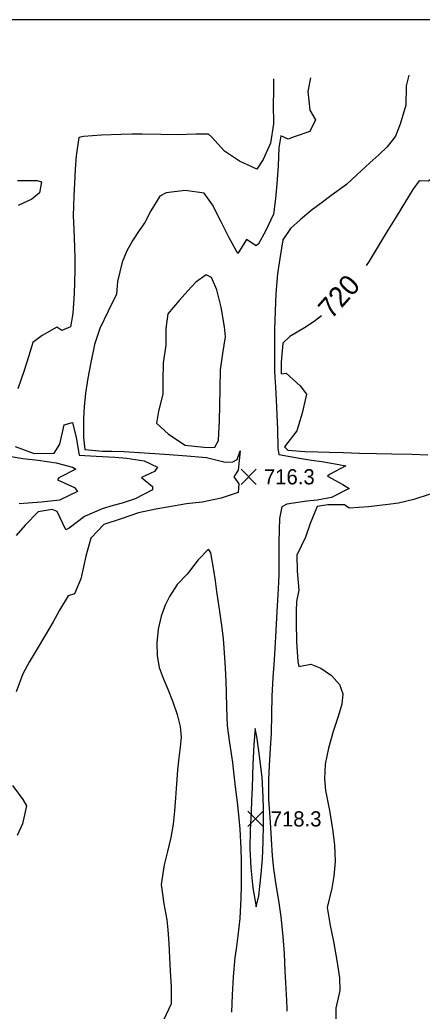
# Model space of a CAD drawing. Extents: x 2566079 to 2571326, y 424054 to 426896.
# Drawn here: x 2569092 to 2569490, y 425896 to 426874 of the extents above; entities that cross this region are included whole.
import ezdxf

# ---------------------------------------------------------------- set-up
doc = ezdxf.new("R2010")
doc.units = 0
for name, color, linetype in [('Contour_ADS_Label_Major', 7, 'Continuous'), ('Contour_ADS_Major', 7, 'Continuous'), ('Contour_ADS_Minor', 7, 'Continuous'), ('Contour_ADS_Spot_Elevation', 7, 'Continuous'), ('Contour_ADS_State_Plane_Border', 7, 'Continuous')]:
    doc.layers.add(name, color=color, linetype=linetype)

# ---------------------------------------------------------------- blocks, each defined once
blk = doc.blocks.new('S750')
at = {"layer": 'Contour_ADS_Spot_Elevation'}
for p, q in [((-0.5, 0.498), (0.5, -0.498)), ((-0.498, -0.5), (0.498, 0.5))]:
    blk.add_line(p, q, dxfattribs=at)

msp = doc.modelspace()

# ---------------------------------------------------------------- linework, layer by layer
at = {"layer": 'Contour_ADS_Major'}
for points in [[(2569582.66, 426821.92), (2569572.1, 426809.88), (2569562, 426794.76), (2569552.24, 426781.55), (2569544.76, 426771.47), (2569537.76, 426762.19), (2569528.08, 426749.94), (2569516.18, 426734.74), (2569508.52, 426725.45), (2569501.28, 426718.14), (2569495.52, 426714.64), (2569486.72, 426714.73), (2569480.41, 426706.26), (2569473.21, 426694.62), (2569463.96, 426679.49), (2569454.21, 426663.45), (2569445.24, 426648.69), (2569437.29, 426635.75), (2569434.53, 426631.41)], [(2569390.27, 426581.56), (2569383.06, 426576.26), (2569373.52, 426569.8), (2569359.02, 426561.22), (2569352.01, 426554.71), (2569350.53, 426536.08), (2569350.39, 426524.49), (2569355.37, 426525.28), (2569369.13, 426512.53), (2569375.37, 426504.58), (2569371.08, 426485.69), (2569366.03, 426468.09), (2569353.78, 426452.3), (2569356.92, 426449.22), (2569373.93, 426448.01), (2569386.62, 426447.52), (2569397.79, 426447.14), (2569411.88, 426446.71), (2569427.83, 426446.27), (2569444.45, 426445.88), (2569459.87, 426445.57), (2569479.69, 426445.26), (2569495.15, 426444.69)], [(2569497.72, 426405.76), (2569481.61, 426400.43), (2569466.45, 426397.04), (2569456.08, 426395.59), (2569436.75, 426393.31), (2569417.6, 426391.93), (2569413.11, 426395.14), (2569396.42, 426395.1), (2569386.08, 426393.6), (2569379.08, 426376.92), (2569374.35, 426363.4), (2569365.75, 426345.5), (2569366.36, 426329.89), (2569368, 426311.08), (2569365.66, 426299.97), (2569365.24, 426290.36), (2569365.2, 426279.42), (2569365.43, 426259.96), (2569366.84, 426240.54), (2569368.02, 426235.84), (2569379.87, 426238.16), (2569389.58, 426234.23), (2569400.09, 426226.88), (2569408.14, 426217.91), (2569411.29, 426208.66), (2569410.27, 426198.49), (2569406.59, 426186.31), (2569401.75, 426171.46), (2569397.11, 426155.19), (2569393.97, 426139.22), (2569393.25, 426125.07), (2569394.21, 426113.52), (2569397.89, 426095.25), (2569399.27, 426087.82), (2569401.23, 426075.39), (2569403.04, 426059.69), (2569403.71, 426043.42), (2569402.58, 426028.95), (2569400.39, 426017.14), (2569395.89, 425997.94), (2569398.72, 425980.35), (2569401.99, 425964.48), (2569405.53, 425945.76), (2569407.94, 425928.51), (2569408.22, 425916.08), (2569404.37, 425898.64), (2569404.52, 425886.62)]]:
    msp.add_lwpolyline(points, dxfattribs=at)
at = {"layer": 'Contour_ADS_Minor'}
for points in [[(2569379.34, 426816.45), (2569376.84, 426803.13), (2569378.88, 426784.63), (2569384.21, 426775.14), (2569378.86, 426763.58), (2569363.21, 426758.17), (2569357.32, 426756.1), (2569350.16, 426759.27), (2569348.16, 426747.33), (2569347.54, 426729.76), (2569346.15, 426712.08), (2569344.78, 426697.61), (2569343, 426681.99), (2569335.01, 426665.34), (2569327.94, 426652.85), (2569325.81, 426650.78), (2569316.12, 426657.05), (2569307.8, 426643.1), (2569299.2, 426658.71), (2569290.97, 426674.99), (2569282.58, 426691.15), (2569274.43, 426702.58), (2569255.56, 426705.27), (2569236.78, 426703.14), (2569230.49, 426699.62), (2569221.72, 426685.18), (2569215.62, 426673.92), (2569210.24, 426665.97), (2569203.99, 426656.47), (2569198.1, 426645.84), (2569193.56, 426634.67), (2569188.9, 426615.74), (2569187.78, 426603.02), (2569179.64, 426586.2), (2569171.32, 426569.24), (2569166.17, 426553.32), (2569161.97, 426534.05), (2569159.4, 426520.06), (2569157.2, 426505.5), (2569155.82, 426492.06), (2569155.15, 426480.54), (2569155.24, 426461.77), (2569156.68, 426449.77), (2569173.97, 426448.15), (2569183.09, 426448.17), (2569195.15, 426447.85), (2569210.07, 426446.99), (2569225.81, 426445.86), (2569239.86, 426444.8), (2569257.34, 426443.71), (2569276.84, 426442.08), (2569295.26, 426437.27), (2569302.84, 426437.73), (2569306.89, 426439.93), (2569309.98, 426448.64), (2569308.09, 426429.57), (2569303.64, 426422.83), (2569308.59, 426416.09), (2569307.87, 426407.46), (2569291.06, 426401.97), (2569272.57, 426397.9), (2569256.99, 426396.07), (2569238.07, 426393.1), (2569226.54, 426390.99), (2569209.56, 426387.48), (2569192.28, 426381.56), (2569175.31, 426375.87), (2569162.52, 426362.38), (2569157.46, 426344.68), (2569155.28, 426334.09), (2569152.42, 426322.29), (2569146.16, 426307.39), (2569140.03, 426305.58), (2569131.47, 426291.17), (2569125.21, 426279.96), (2569117.67, 426266.94), (2569109.44, 426253.28), (2569101.6, 426240.1), (2569095.34, 426228.48), (2569088.8, 426210.91)], [(2569342.98, 426815.47), (2569342.95, 426814.32), (2569342.75, 426802.86), (2569342.59, 426790.61), (2569342.89, 426771.28), (2569340.01, 426752.15), (2569332.75, 426735.88), (2569326.41, 426726.35), (2569309.39, 426734.31), (2569294.46, 426744.03), (2569281.97, 426757.86), (2569278.8, 426761.01), (2569266.17, 426760.86), (2569248.33, 426760.28), (2569231.43, 426760.76), (2569213.07, 426761.04), (2569202.82, 426760.85), (2569192.42, 426760.54), (2569173.14, 426759.83), (2569155.28, 426758.6), (2569150.74, 426757.59), (2569147.95, 426739.46), (2569147.02, 426726.42), (2569146.19, 426712.7), (2569145.57, 426700.19), (2569145.1, 426680.5), (2569145.6, 426666.83), (2569146.35, 426649.52), (2569146.56, 426638.23), (2569146.57, 426626.35), (2569146.33, 426614.75), (2569145.89, 426603.7), (2569144.68, 426583.99), (2569142.5, 426571), (2569133.87, 426567.35), (2569128.72, 426570.58), (2569114.47, 426562.42), (2569105.09, 426555.36), (2569100.86, 426541.17), (2569096.57, 426527.86), (2569090.36, 426509.57)], [(2569476.47, 426819.06), (2569473.79, 426808.46), (2569473.44, 426789.51), (2569467.96, 426770.96), (2569463.49, 426759.05), (2569455.07, 426748.28), (2569447.05, 426740.64), (2569438.04, 426732.6), (2569425.32, 426720.96), (2569414.91, 426711.42), (2569399.53, 426700.02), (2569389.82, 426692.85), (2569380.2, 426685.47), (2569369.07, 426676.51), (2569359.6, 426668.01), (2569351.92, 426656.7), (2569349.04, 426638.33), (2569346.92, 426623.02), (2569345.24, 426603.68), (2569344.35, 426586.26), (2569343.72, 426568.63), (2569343.73, 426558), (2569343.81, 426546.07), (2569343.99, 426526.37), (2569345, 426511.48), (2569345.59, 426498.75), (2569346.23, 426483.68), (2569346.75, 426469.99), (2569347.18, 426451.15), (2569348.14, 426445.01), (2569366.57, 426441.53), (2569380.36, 426439.45), (2569390.58, 426437.83), (2569407.32, 426435.1), (2569414.2, 426433.59), (2569398.32, 426425.24), (2569396.07, 426423.6), (2569411.49, 426415.32), (2569417.68, 426411.4), (2569400.15, 426402.51), (2569386.08, 426399.94), (2569375.7, 426398.8), (2569355.98, 426395.79), (2569351.06, 426393.32), (2569348.74, 426381.6), (2569348.51, 426370.6), (2569348.26, 426358.46), (2569348.29, 426338.81), (2569348.15, 426326.68), (2569347.79, 426318.68), (2569347.18, 426306.64), (2569346.26, 426290.12), (2569345.17, 426271.32), (2569344.07, 426253.03), (2569343.1, 426237.55), (2569342.3, 426224.95), (2569341.24, 426206.54), (2569340.96, 426188.22), (2569340.56, 426170.13), (2569339.72, 426154.75), (2569338.68, 426137.94), (2569337.81, 426123.86), (2569338.06, 426104.39), (2569338.59, 426096.02), (2569339.41, 426082.16), (2569340.46, 426065.36), (2569341.65, 426049.08), (2569342.9, 426036.08), (2569345.39, 426018.23), (2569347.77, 426004.82), (2569350.1, 425988.61), (2569352.12, 425969.24), (2569353.29, 425952.59), (2569353.99, 425935.04), (2569354.55, 425923.97), (2569355.57, 425906.24)], [(2569089.89, 426715.21), (2569109.47, 426715.37), (2569113.75, 426714.04), (2569111.8, 426702.91), (2569104.19, 426696.93), (2569090.75, 426690.64)], [(2569087.81, 426452.75), (2569106.55, 426445.98), (2569126.37, 426446.09), (2569131.85, 426454.96), (2569135.99, 426474.28), (2569144.33, 426476.31), (2569147.9, 426461.62), (2569151.01, 426444.34), (2569167.83, 426443.37), (2569186.26, 426442.29), (2569198.04, 426441.21), (2569215.08, 426438.5), (2569228.14, 426432.32), (2569225.43, 426428.17), (2569212.43, 426422.19), (2569223.29, 426413.18), (2569223.32, 426410.01), (2569206.33, 426401.04), (2569193.28, 426396.94), (2569184.37, 426394.59), (2569173.67, 426391.42), (2569156.36, 426383.7), (2569140.91, 426372.13), (2569137.6, 426370.67), (2569129.16, 426388.6), (2569124.32, 426390.54), (2569110.53, 426388.21), (2569097.47, 426375.07), (2569088.74, 426364.89)], [(2569078.09, 426443.98), (2569095.39, 426440.8), (2569110.57, 426439.22), (2569128.2, 426436.66), (2569144.5, 426432.28), (2569147.56, 426430.31), (2569130.76, 426421.81), (2569129.68, 426419.94), (2569146.39, 426412.45), (2569149.21, 426408.26), (2569131.59, 426399.7), (2569113.57, 426397.87), (2569100.47, 426396.95), (2569091.64, 426396.19)], [(2569301.66, 425894.59), (2569302.36, 425911.72), (2569303.24, 425929.42), (2569305.08, 425948.73), (2569306.52, 425959.34), (2569308.04, 425969.87), (2569310.06, 425987.22), (2569311.01, 426007.12), (2569311.3, 426020.13), (2569311.35, 426031.32), (2569311.29, 426044.05), (2569311.09, 426056.11), (2569310.05, 426075.18), (2569309.01, 426085.79), (2569307.53, 426099.27), (2569305.81, 426114.27), (2569304.09, 426128.67), (2569302.57, 426140.89), (2569299.86, 426160.52), (2569297.35, 426177.13), (2569296.64, 426195.26), (2569296.47, 426210.02), (2569296.07, 426221.08), (2569295.45, 426234.5), (2569294.57, 426249.08), (2569293.39, 426263.34), (2569291.9, 426276.17), (2569290.24, 426287.79), (2569288.54, 426298.8), (2569286.94, 426309.67), (2569285.44, 426320.35), (2569284, 426330.71), (2569280.85, 426347.88), (2569278.55, 426351.66), (2569268.49, 426341.01), (2569257.6, 426326.92), (2569247.86, 426316.73), (2569240.31, 426304.87), (2569235.87, 426296.14), (2569231.89, 426285.37), (2569229.02, 426272.67), (2569227.61, 426259.18), (2569227.93, 426246.28), (2569230.1, 426234.91), (2569233.75, 426224.31), (2569238.38, 426213.28), (2569243.39, 426201.02), (2569247.88, 426188.34), (2569250.81, 426176.42), (2569251.51, 426166.03), (2569250.65, 426156.25), (2569249.22, 426145.69), (2569248.03, 426133.39), (2569247.09, 426119.94), (2569246.22, 426106.29), (2569245.23, 426093.18), (2569243.77, 426080.29), (2569241.48, 426067.06), (2569238.26, 426053.25), (2569234.92, 426040), (2569231.88, 426020.56), (2569234.5, 426001.61), (2569237.53, 425985.81), (2569238.63, 425975.78), (2569239.5, 425962.59), (2569240.17, 425948.29), (2569240.71, 425935.46), (2569241.67, 425919.36), (2569241.93, 425903.03), (2569234.71, 425887.44)], [(2569085.12, 426118.32), (2569095.29, 426104.63), (2569098.85, 426098.18), (2569094.9, 426080.54), (2569089.62, 426068.93)]]:
    msp.add_lwpolyline(points, dxfattribs=at)
for points in [[(2569280.24, 426451.71), (2569284.88, 426452.1), (2569288.52, 426458.85), (2569289.5, 426478.65), (2569289.73, 426492.84), (2569290.05, 426510.14), (2569290.49, 426528.29), (2569292.97, 426544.49), (2569295.32, 426560.95), (2569294.62, 426570.93), (2569291.09, 426590.09), (2569286.95, 426607.38), (2569281.56, 426619.68), (2569276.24, 426622.25), (2569266.12, 426614.86), (2569258.12, 426606.39), (2569249.63, 426596.77), (2569238.5, 426583.53), (2569236.56, 426569.26), (2569236.55, 426552.8), (2569233.87, 426535.43), (2569233.5, 426517.61), (2569233.6, 426504.42), (2569229.16, 426487.61), (2569227.43, 426475.92), (2569239.26, 426464.86), (2569255.7, 426453.97), (2569274.12, 426452.21), (2569280.24, 426451.71)], [(2569323.51, 426158.46), (2569322.42, 426138.94), (2569322.08, 426128.36), (2569321.72, 426115.98), (2569321.28, 426103.45), (2569320.75, 426092.17), (2569319.72, 426074.74), (2569319.41, 426056.18), (2569320.32, 426037.06), (2569322.44, 426017.34), (2569325.88, 425998.49), (2569328.22, 426009.64), (2569329.43, 426018.66), (2569330.8, 426031), (2569331.98, 426046.04), (2569332.69, 426062.92), (2569332.98, 426079.92), (2569332.98, 426095.08), (2569332.78, 426107.06), (2569331.52, 426126.48), (2569330.33, 426136.89), (2569328.93, 426147.7), (2569326.42, 426166.75), (2569324.81, 426174.56), (2569323.51, 426158.46)]]:
    msp.add_lwpolyline(points, close=True, dxfattribs=at)
msp.add_arc((2593553.12, 427300.05), 24237.66, 183.296661, 183.321642, dxfattribs=at)
at = {"layer": 'Contour_ADS_State_Plane_Border'}
msp.add_lwpolyline([(2566079.33, 424077.11), (2571302.93, 424077.11), (2571302.93, 426873.74), (2566079.33, 426873.74), (2566079.33, 424077.11)], close=True, dxfattribs=at)

# ---------------------------------------------------------------- block references
at = {"layer": 'Contour_ADS_Spot_Elevation', "xscale": 15, "yscale": 15}
for p in [(2569318.38, 426422.91), (2569325.07, 426085.4)]:
    msp.add_blockref('S750', p, dxfattribs=at)

# ---------------------------------------------------------------- texts
at = {"layer": 'Contour_ADS_Label_Major'}
msp.add_text('720', height=20, rotation=48.3984, dxfattribs=at).set_placement((2569400.14, 426577.62))
at = {"layer": 'Contour_ADS_Spot_Elevation'}
for s, p in [('716.3', (2569333.38, 426415.41)), ('718.3', (2569340.07, 426077.9))]:
    msp.add_text(s, height=15, dxfattribs=at).set_placement(p)

doc.saveas('drawing.dxf')
